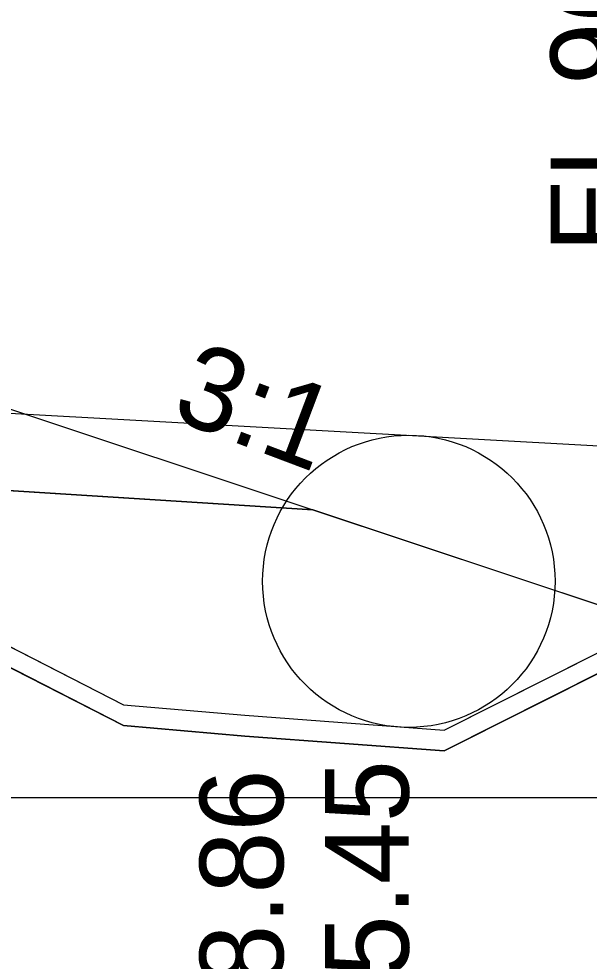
# Model space of a CAD drawing. Extents: x -192 to 2669, y -25 to 8040.
# Drawn here: x 165.34 to 172.16, y 4998.04 to 5009.33 of the extents above; entities that cross this region are included whole.
import ezdxf

# ---------------------------------------------------------------- set-up
doc = ezdxf.new("R2010")
doc.units = 0
for name, color, linetype in [('DESIGN - EARTHWORK - Shapes', 7, 'Continuous'), ('DESIGN - SCRATCH - User 2', 7, 'Continuous'), ('DESIGN - SHEET - Light Grid', 7, 'Continuous'), ('DESIGN - TYPICAL - Finished Grade and Subgrade', 7, 'Continuous'), ('DESIGN - TYPICAL - Finished Grade Slopes Text', 7, 'Continuous'), ('DESIGN - TYPICAL - Slope Tie Text', 7, 'Continuous'), ('DESIGN - TYPICAL - Subgrade Tie Text', 7, 'Continuous'), ('SURVEY - GROUND - Bottom of Topsoil Layer', 7, 'Continuous'), ('SURVEY - GROUND - Top of Ground', 7, 'Continuous')]:
    doc.layers.add(name, color=color, linetype=linetype)

msp = doc.modelspace()

# ---------------------------------------------------------------- linework, layer by layer
at = {"layer": 'DESIGN - EARTHWORK - Shapes'}
for points in [[(161.072, 5003.941), (166.591, 5001.111), (168.044, 5000.986), (170.43, 5000.808), (172.342, 5001.771), (172.342, 5001.521), (170.43, 5000.558), (168.044, 5000.736), (166.591, 5000.861), (160.515, 5003.977)], [(161.072, 5003.941), (166.591, 5001.111), (168.044, 5000.986), (170.43, 5000.808), (172.342, 5001.771), (172.342, 5002.286), (168.859, 5003.447), (162, 5003.882)]]:
    msp.add_lwpolyline(points, close=True, dxfattribs=at)
at = {"layer": 'DESIGN - SCRATCH - User 2'}
msp.add_line((155.178, 5005.159), (175.07, 5004.06), dxfattribs=at)
msp.add_circle((170.007, 5002.59), 1.75, dxfattribs=at)
at = {"layer": 'DESIGN - SHEET - Light Grid'}
msp.add_line((150, 5000), (300, 5000), dxfattribs=at)
at = {"layer": 'DESIGN - TYPICAL - Finished Grade and Subgrade'}
for p, q in [((164, 5005.066), (168.859, 5003.447)), ((162, 5003.882), (168.859, 5003.447)), ((168.859, 5003.447), (174.736, 5001.488))]:
    msp.add_line(p, q, dxfattribs=at)
at = {"layer": 'SURVEY - GROUND - Bottom of Topsoil Layer'}
for p, q in [((170.43, 5000.558), (179.297, 5005.026)), ((160.468, 5004.001), (166.591, 5000.861)), ((166.591, 5000.861), (168.044, 5000.736)), ((168.044, 5000.736), (170.43, 5000.558))]:
    msp.add_line(p, q, dxfattribs=at)
at = {"layer": 'SURVEY - GROUND - Top of Ground'}
msp.add_lwpolyline([(51.693, 5003.966), (90.066, 5005.095), (91.975, 5005.103), (113.762, 5004.843), (117.818, 5004.728), (119.269, 5004.239), (124.315, 5002.461), (127.63, 5004.22), (132.95, 5006.602), (140.366, 5006.218), (143.386, 5006.149), (150, 5005.636), (153.47, 5005.343), (155.178, 5005.159), (159.938, 5004.517), (160.468, 5004.251), (166.591, 5001.111), (168.044, 5000.986), (170.43, 5000.808), (179.297, 5005.276), (179.647, 5005.45), (180.314, 5005.482), (200.525, 5005.969)], dxfattribs=at)

# ---------------------------------------------------------------- texts
at = {"layer": 'DESIGN - TYPICAL - Finished Grade Slopes Text'}
msp.add_text('3:1', height=1, rotation=339.3166, dxfattribs=at).set_placement((167.138, 5004.55))
at = {"layer": 'DESIGN - TYPICAL - Slope Tie Text'}
msp.add_text('EL.964.08', height=1, rotation=90, dxfattribs=at).set_placement((172.703, 5006.529))
at = {"layer": 'DESIGN - TYPICAL - Subgrade Tie Text'}
for s, p in [('EL.965.45', (170.005, 4994.351)), ('OFFSET 18.86', (168.505, 4991.344))]:
    msp.add_text(s, height=1, rotation=90, dxfattribs=at).set_placement(p)

doc.saveas('drawing.dxf')
